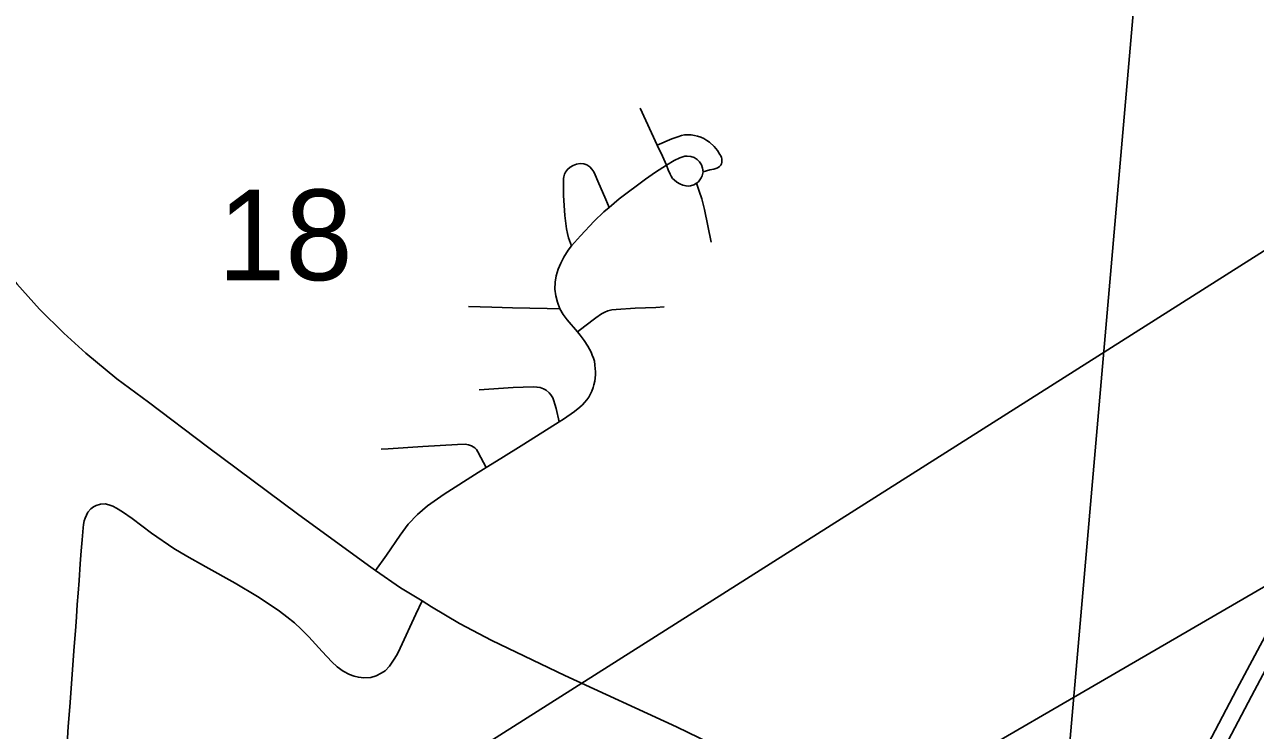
# Model space of a CAD drawing. Extents: x 0 to 34, y 0 to 22.
# Drawn here: x 6.814 to 7.382, y 19.509 to 19.835 of the extents above; entities that cross this region are included whole.
import ezdxf

# ---------------------------------------------------------------- set-up
doc = ezdxf.new("R2010")
doc.units = 0
for name, color, linetype in [('GM_X_County_Road', 7, 'Continuous'), ('GM_X_Section', 7, 'Continuous'), ('GM_X_Section_Text', 7, 'Continuous'), ('GM_X_State_Route', 7, 'Continuous'), ('GM_X_Township_Road', 7, 'Continuous'), ('SH_Text', 7, 'Continuous')]:
    doc.layers.add(name, color=color, linetype=linetype)

msp = doc.modelspace()

# ---------------------------------------------------------------- linework, layer by layer
at = {"layer": 'GM_X_County_Road'}
for points in [[(7.24494, 19.28406), (7.25979, 19.31381), (7.27937, 19.35301), (7.29524, 19.38386), (7.30856, 19.40814), (7.31018, 19.411), (7.31397, 19.41772), (7.33222, 19.44909), (7.37357, 19.52803), (7.40567, 19.58831), (7.41026, 19.59712), (7.41066, 19.59791), (7.41237, 19.60055), (7.41345, 19.6018), (7.41498, 19.6031), (7.41678, 19.60423), (7.41938, 19.60547)], [(7.32163, 19.41383), (7.35119, 19.46947), (7.38041, 19.52488), (7.41717, 19.59412), (7.41859, 19.5975), (7.41932, 19.60089), (7.41955, 19.60316), (7.41938, 19.60547)]]:
    msp.add_lwpolyline(points, dxfattribs=at)
at = {"layer": 'GM_X_Section'}
for points in [[(7.35437, 20.16973), (7.26758, 19.17046), (6.2677, 19.26674), (6.34458, 20.2616)], [(8.36301, 20.07599), (8.27199, 19.07297), (7.26758, 19.17046), (7.35437, 20.16973)]]:
    msp.add_lwpolyline(points, close=True, dxfattribs=at)
at = {"layer": 'GM_X_State_Route'}
for points in [[(6.9759, 19.58283), (6.97262, 19.5851), (6.93986, 19.60895), (6.89821, 19.64002), (6.871, 19.66052), (6.85639, 19.67143), (6.84212, 19.68319), (6.83187, 19.69242), (6.82062, 19.70351), (6.8102, 19.71526), (6.80332, 19.72417), (6.79758, 19.73229), (6.79029, 19.74262), (6.78525, 19.75064), (6.77846, 19.7623), (6.7714, 19.7759), (6.76687, 19.78648), (6.76318, 19.79522), (6.75864, 19.80831), (6.75305, 19.82861), (6.75172, 19.83444)], [(7.14561, 19.49575), (7.11488, 19.5107), (7.06332, 19.53438), (7.02956, 19.5505), (7.01461, 19.55839), (7.00167, 19.56612), (6.99733, 19.56878), (6.9874, 19.57485), (6.9759, 19.58283)]]:
    msp.add_lwpolyline(points, dxfattribs=at)
at = {"layer": 'GM_X_Township_Road'}
msp.add_line((7.10594, 19.77929), (7.09803, 19.79637), dxfattribs=at)
for points in [[(7.12707, 19.76702), (7.13024, 19.76783), (7.13203, 19.76824), (7.1334, 19.76863), (7.13413, 19.76898), (7.13474, 19.76942), (7.13527, 19.76998), (7.13564, 19.77067), (7.13578, 19.77139), (7.13582, 19.77215), (7.13574, 19.77294), (7.13555, 19.77364), (7.13528, 19.77429), (7.13491, 19.77502), (7.13376, 19.77687), (7.13226, 19.77869), (7.13, 19.78074), (7.12888, 19.78145), (7.12741, 19.78235), (7.12612, 19.78291), (7.12457, 19.78344), (7.1231, 19.78376), (7.12157, 19.78401), (7.11999, 19.78411), (7.11853, 19.78403), (7.11717, 19.78376), (7.11541, 19.78315), (7.1127, 19.78215), (7.10594, 19.77929)], [(7.11022, 19.77004), (7.10831, 19.77416), (7.10594, 19.77929)], [(7.11022, 19.77004), (7.11383, 19.77215), (7.11639, 19.77348), (7.11768, 19.77394), (7.11873, 19.77416), (7.11973, 19.77421), (7.12139, 19.77406), (7.123, 19.77361), (7.12435, 19.7727), (7.12541, 19.7716), (7.12632, 19.77024), (7.12687, 19.76868), (7.12707, 19.76702)], [(7.06637, 19.73273), (7.06499, 19.7365), (7.06443, 19.73851), (7.06401, 19.74068), (7.06326, 19.74682), (7.06266, 19.7561), (7.0626, 19.76231), (7.06271, 19.76387), (7.06284, 19.76473), (7.06315, 19.76592), (7.06362, 19.76688), (7.06449, 19.76807), (7.06578, 19.76912), (7.06719, 19.76995), (7.06867, 19.7705), (7.07038, 19.77075), (7.07199, 19.7706), (7.07341, 19.77016), (7.07476, 19.76927), (7.0758, 19.76824), (7.0766, 19.76691), (7.0773, 19.76555), (7.07844, 19.76266), (7.08214, 19.75413), (7.08371, 19.75053)], [(7.08371, 19.75053), (7.08838, 19.75452), (7.10044, 19.76356), (7.10516, 19.76688), (7.11022, 19.77004)], [(7.12406, 19.7617), (7.12282, 19.761), (7.12134, 19.76053), (7.12027, 19.76038), (7.11926, 19.76046), (7.11777, 19.76079), (7.11631, 19.76138), (7.11496, 19.76225), (7.1138, 19.76321), (7.11304, 19.76392), (7.11237, 19.7649), (7.11184, 19.76588), (7.11104, 19.76788), (7.11022, 19.77004)], [(7.12707, 19.76702), (7.12662, 19.76512), (7.12622, 19.76421), (7.12567, 19.76326), (7.12496, 19.7624), (7.12406, 19.7617)], [(7.13089, 19.73441), (7.12783, 19.74951), (7.12652, 19.75457), (7.12536, 19.75802), (7.12406, 19.7617)], [(7.06637, 19.73273), (7.07048, 19.73736), (7.07685, 19.74417), (7.08132, 19.74848), (7.08371, 19.75053)], [(7.06091, 19.70371), (7.05982, 19.70673), (7.05909, 19.70975), (7.05871, 19.71284), (7.05873, 19.71594), (7.05922, 19.719), (7.06013, 19.72198), (7.06135, 19.72484), (7.06286, 19.72755), (7.06481, 19.73072), (7.06637, 19.73273)], [(7.01883, 19.70478), (7.02951, 19.7045), (7.03912, 19.70421), (7.05508, 19.70385), (7.06091, 19.70371)], [(7.06914, 19.69304), (7.07254, 19.69568), (7.07758, 19.6996), (7.0802, 19.70143), (7.0817, 19.7022), (7.08308, 19.70274), (7.08493, 19.70318), (7.08692, 19.70346), (7.09573, 19.70397), (7.10532, 19.70435), (7.10915, 19.70459)], [(7.06914, 19.69304), (7.06429, 19.69864), (7.06244, 19.70113), (7.06091, 19.70371)], [(7.06072, 19.65153), (7.06268, 19.65277), (7.0678, 19.6563), (7.07022, 19.65827), (7.07139, 19.65938), (7.07241, 19.66044), (7.07341, 19.66161), (7.07428, 19.66293), (7.07517, 19.66449), (7.07572, 19.66567), (7.07632, 19.66733), (7.07673, 19.66861), (7.07711, 19.67031), (7.0773, 19.67167), (7.07738, 19.6733), (7.0774, 19.67478), (7.07734, 19.67599), (7.07717, 19.67785), (7.07689, 19.67945), (7.07645, 19.68086), (7.07596, 19.68229), (7.07535, 19.68374), (7.07393, 19.68649), (7.07226, 19.6891), (7.0704, 19.69158), (7.06914, 19.69304)], [(7.02372, 19.66634), (7.03934, 19.66733), (7.04872, 19.66769), (7.05039, 19.66758), (7.05182, 19.6673), (7.05341, 19.66679), (7.05466, 19.66606), (7.05596, 19.66496), (7.05686, 19.66395), (7.05772, 19.66262), (7.05823, 19.66125), (7.05868, 19.65974), (7.0592, 19.65766), (7.06072, 19.65153)], [(7.02701, 19.63043), (7.03376, 19.63459), (7.0443, 19.64116), (7.06072, 19.65153)], [(6.97849, 19.63895), (6.98166, 19.63907), (6.99766, 19.64009), (7.01363, 19.6411), (7.01717, 19.64119), (7.01799, 19.6411), (7.0188, 19.64094), (7.02018, 19.64041), (7.021, 19.63999), (7.02169, 19.63953), (7.02241, 19.63875), (7.02309, 19.63762), (7.02448, 19.63508), (7.02701, 19.63043)], [(6.9759, 19.58283), (6.98086, 19.59), (6.98726, 19.59923), (6.99096, 19.6042), (6.99517, 19.60875), (6.99986, 19.61278), (7.00748, 19.61812), (7.02319, 19.62809), (7.02701, 19.63043)], [(6.83321, 19.50057), (6.83358, 19.50546), (6.83398, 19.51078), (6.83466, 19.51989), (6.8356, 19.5326), (6.83659, 19.54579), (6.83743, 19.55702), (6.83774, 19.56146), (6.83815, 19.56713), (6.83852, 19.57244), (6.83895, 19.57816), (6.83953, 19.58588), (6.83998, 19.59189), (6.84037, 19.59698), (6.84079, 19.60259), (6.84103, 19.60413), (6.84136, 19.60571), (6.84177, 19.60695), (6.84232, 19.60843), (6.84305, 19.60974), (6.84436, 19.61127), (6.84562, 19.61226), (6.84691, 19.61291), (6.84883, 19.61344)], [(6.99733, 19.56878), (6.99447, 19.56261), (6.9872, 19.54694), (6.98578, 19.54412), (6.9841, 19.5414), (6.98227, 19.53871), (6.98024, 19.53651), (6.97853, 19.53537), (6.9761, 19.53415), (6.97373, 19.5335), (6.97048, 19.53334), (6.96796, 19.53358), (6.96593, 19.53407), (6.96382, 19.53489), (6.96097, 19.53643), (6.95821, 19.53838), (6.9556, 19.54066), (6.95121, 19.54538), (6.94503, 19.5522), (6.94153, 19.5557), (6.93837, 19.55871), (6.93495, 19.56148), (6.93153, 19.56408), (6.9286, 19.56611), (6.92128, 19.57083), (6.91103, 19.57702), (6.89753, 19.58456), (6.88876, 19.58945), (6.88274, 19.59303), (6.87241, 19.6001), (6.86347, 19.60685), (6.859, 19.60994), (6.85631, 19.61165), (6.85452, 19.61255), (6.85264, 19.61325), (6.85095, 19.6136), (6.84883, 19.61344)]]:
    msp.add_lwpolyline(points, dxfattribs=at)
at = {"layer": 'SH_Text'}
msp.add_lwpolyline([(9.2218, 20.89411), (4.45803, 17.87452), (9.2218, 20.64169)], close=True, dxfattribs=at)

# ---------------------------------------------------------------- texts
at = {"layer": 'GM_X_Section_Text'}
msp.add_text('18', height=0.041856, rotation=0, dxfattribs=at).set_placement((6.90304, 19.71692))

doc.saveas('drawing.dxf')
